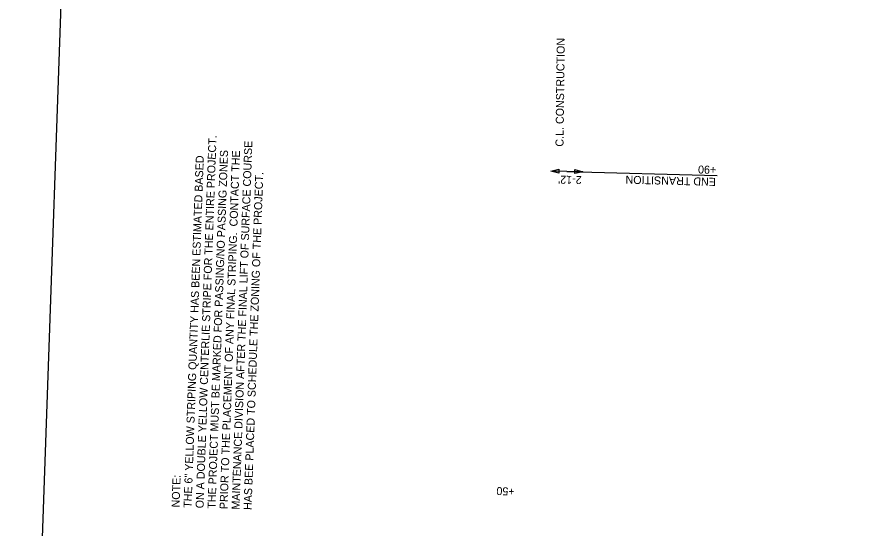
# Model space of a CAD drawing. Extents: x 633912 to 634995, y 289794 to 291427.
# Drawn here: x 633912 to 634549, y 290387 to 290770 of the extents above; entities that cross this region are included whole.
import ezdxf

# ---------------------------------------------------------------- set-up
doc = ezdxf.new("R2010")
doc.units = 0
for name, color, linetype in [('Level 63', 7, 'Continuous'), ('R_Dimension', 7, 'Continuous'), ('ROAD', 7, 'Continuous')]:
    doc.layers.add(name, color=color, linetype=linetype)

msp = doc.modelspace()

# ---------------------------------------------------------------- linework, layer by layer
at = {"layer": 'Level 63'}
msp.add_lwpolyline([(634938.65, 289793.65), (633912.26, 289829.49), (633957.19, 291116.06), (634006.28, 291114.34), (634017.21, 291427.35), (634994.51, 291393.22)], close=True, dxfattribs=at)
at = {"layer": 'R_Dimension'}
msp.add_line((634336.42, 290654.34), (634312.43, 290654.77), dxfattribs=at)
for points in [[(634318.4, 290653.16), (634312.43, 290654.77), (634318.45, 290656.16)], [(634330.45, 290655.94), (634336.42, 290654.34), (634330.4, 290652.94)]]:
    msp.add_lwpolyline(points, close=True, dxfattribs=at)
at = {"layer": 'ROAD'}
msp.add_line((634437.15, 290651.36), (634324.41, 290654.17), dxfattribs=at)

# ---------------------------------------------------------------- texts
at = {"layer": 'R_Dimension'}
for s, rotation, p in [('C.L. CONSTRUCTION', 89.30259, (634321.9, 290673.14)), ("2-12'", 179.15862, (634335.59, 290651.13))]:
    msp.add_text(s, height=6, rotation=rotation, dxfattribs=at).set_placement(p)
at = {"layer": 'ROAD'}
for s, rotation, p in [('ON A DOUBLE YELLOW CENTERLIE STRIPE FOR THE ENTIRE PROJECT.', 87.99913, (634052.09, 290401.76)), ('MAINTENANCE DIVISION AFTER THE FINAL LIFT OF SURFACE COURSE', 87.99913, (634079.07, 290400.82)), ('THE 6" YELLOW STRIPING QUANTITY HAS BEEN ESTIMATED BASED', 87.99913, (634043.09, 290402.08)), ('THE PROJECT MUST BE MARKED FOR PASSING/NO PASSING ZONES', 87.99913, (634061.08, 290401.45)), ('PRIOR TO THE PLACEMENT OF ANY FINAL STRIPING.  CONTACT THE', 87.99913, (634070.08, 290401.13)), ('HAS BEE PLACED TO SCHEDULE THE ZONING OF THE PROJECT.', 87.99913, (634088.07, 290400.51)), ('+90', 178.57099, (634436.46, 290658.71)), ('END TRANSITION', 178.57099, (634436.23, 290649.72)), ('NOTE:', 87.99913, (634034.1, 290402.39)), ('+50', 177.06713, (634285.39, 290417.22))]:
    msp.add_text(s, height=6, rotation=rotation, dxfattribs=at).set_placement(p)

doc.saveas('drawing.dxf')
